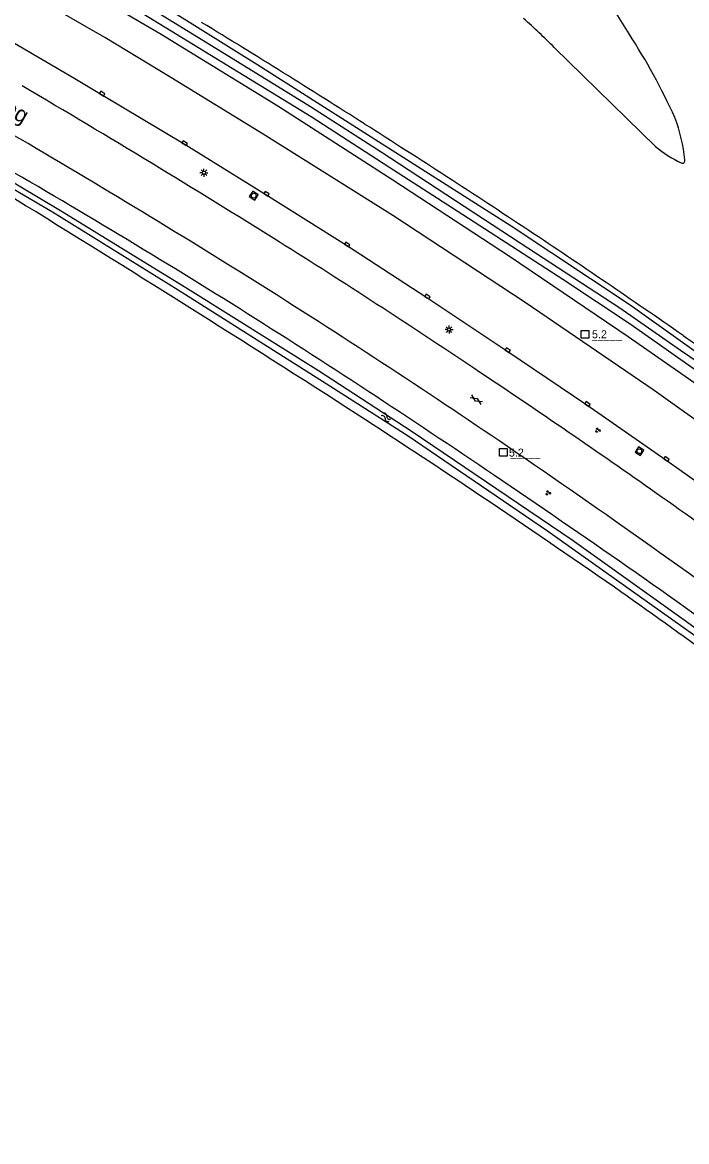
# Model space of a CAD drawing. Extents: x 133000 to 136000, y 400500 to 403500.
# Drawn here: x 134801.3 to 134905.2, y 400816.9 to 400991.7 of the extents above; entities that cross this region are included whole.
import ezdxf

# ---------------------------------------------------------------- set-up
doc = ezdxf.new("R2010")
doc.units = 0
for name, color, linetype in [('gg-afsc-erfafscheiding', 7, 'Continuous'), ('gg-anno-openbare ruimte label', 7, 'Continuous'), ('gg-knt-verharding', 7, 'Continuous'), ('gg-kntw-bovenkant insteek waterloop', 7, 'Continuous'), ('gg-kntw-waterlijn', 7, 'Continuous'), ('gt-anno-nummer hm paal', 7, 'Continuous'), ('gt-symb-gesloten verharding', 7, 'Continuous'), ('gt-symb-groenvak', 7, 'Continuous'), ('gt-symb-hm paal', 7, 'Continuous'), ('gt-symb-kolk', 7, 'Continuous'), ('gt-symb-lichtmast', 7, 'Continuous'), ('gt-symb-rioolschacht', 7, 'Continuous'), ('gt-symb-watersymbool', 7, 'Continuous')]:
    doc.layers.add(name, color=color, linetype=linetype)

# ---------------------------------------------------------------- blocks, each defined once
blk = doc.blocks.new('gt0-RS')
at = {"layer": 'gt-symb-rioolschacht'}
blk.add_lwpolyline([(-0.5, -0.5), (0.5, -0.5), (0.5, 0.5), (-0.5, 0.5)], close=True, dxfattribs=at)
blk.add_circle((0, 0), 0.375, dxfattribs=at)
blk = doc.blocks.new('gt0-KOLK')
at = {"layer": 'gt-symb-kolk'}
blk.add_lwpolyline([(0, 0), (0.38, 0), (0.38, 0.4), (-0.37, 0.4), (-0.37, 0), (0, 0)], dxfattribs=at)
blk = doc.blocks.new('gt0-LMAST')
at = {"layer": 'gt-symb-lichtmast'}
for p, q in [((-0.18, 0.17), (-0.45, 0.44)), ((-0.01, 0.25), (-0.01, 0.62)), ((0.17, 0.17), (0.44, 0.44)), ((-0.26, 0), (-0.63, 0)), ((-0.18, -0.18), (-0.45, -0.45)), ((-0.01, -0.25), (-0.01, -0.63)), ((0.44, -0.45), (0.17, -0.18)), ((0.24, 0), (0.62, 0))]:
    blk.add_line(p, q, dxfattribs=at)
blk.add_circle((-0.01, 0), 0.25, dxfattribs=at)
blk = doc.blocks.new('gt0-WA')
at = {"layer": 'gt-symb-watersymbool'}
for centre, start, end in [((-0.32, 0.02), 28.0725, 151.9275), ((0.43, 0.42), 208.0725, 331.9275), ((-0.32, -0.43), 28.0725, 151.9275), ((0.43, -0.03), 208.0725, 331.9275)]:
    blk.add_arc(centre, 0.425, start, end, dxfattribs=at)
blk = doc.blocks.new('gt0-GESVH1')
at = {"layer": 'gt-symb-gesloten verharding'}
for p, q in [((-0.99, -0.26), (0.01, 0.24)), ((0.01, -0.26), (-0.99, 0.24)), ((0.01, 0.24), (1.01, -0.26)), ((1.01, 0.24), (0.01, -0.26))]:
    blk.add_line(p, q, dxfattribs=at)
blk = doc.blocks.new('gt0-HMpaal')
at = {"layer": 'gt-symb-hm paal'}
blk.add_lwpolyline([(-0.6, 0.6), (0.6, 0.6), (0.6, -0.6), (-0.6, -0.6)], close=True, dxfattribs=at)
blk = doc.blocks.new('gt0-GRVAK')
at = {"layer": 'gt-symb-groenvak'}
for p, q in [((-0.11, 0.19), (-0.23, 0.24)), ((-0.18, 0.15), (0.09, 0.15)), ((-0.09, 0.21), (-0.16, 0.32)), ((-0.05, 0.21), (-0.05, 0.39)), ((0, 0.21), (0.06, 0.32)), ((0.01, 0.19), (0.13, 0.24)), ((0.26, -0.05), (0.2, 0.06)), ((0.3, -0.05), (0.3, 0.13)), ((0.35, -0.05), (0.41, 0.06)), ((-0.25, -0.23), (-0.36, -0.18)), ((-0.32, -0.26), (-0.05, -0.26)), ((-0.23, -0.21), (-0.29, -0.1)), ((-0.18, -0.2), (-0.18, -0.02)), ((-0.14, -0.21), (-0.07, -0.1)), ((-0.12, -0.23), (0, -0.18)), ((0.24, -0.07), (0.12, -0.02)), ((0.17, -0.11), (0.44, -0.11)), ((0.37, -0.07), (0.49, -0.02))]:
    blk.add_line(p, q, dxfattribs=at)

msp = doc.modelspace()

# ---------------------------------------------------------------- linework, layer by layer
at = {"layer": 'gg-afsc-erfafscheiding'}
for centre, radius, start, end in [((133915.2, 399495.67), 1753.25, 57.59278, 58.5737), ((134035.42, 399683.29), 1530.41, 56.48284, 57.62804), ((134114.37, 399807.84), 1382.99, 55.15162, 56.36061), ((133893.12, 399490.22), 1770.06, 54.18342, 55.14896)]:
    msp.add_arc(centre, radius, start, end, dxfattribs=at)
at = {"layer": 'gg-knt-verharding'}
for points in [[(135047.77, 400816.94), (135039.36, 400824.61), (135022.23, 400839.75), (135004.62, 400854.74), (134988.43, 400868.12), (134972.48, 400880.91), (134956.04, 400893.75), (134938.53, 400906.75), (134919.76, 400920.26), (134900.07, 400934.25), (134879.94, 400948), (134859.25, 400961.57), (134838.99, 400974.25), (134824.54, 400983.12), (134814.2, 400989.37), (134794.13, 401000.94), (134771.38, 401013.57), (134759.94, 401019.66)], [(135009.27, 400840.64), (134993.24, 400854.08), (134974.39, 400869.55), (134974.19, 400869.29), (134967.74, 400874.43), (134955.43, 400883.98), (134938.38, 400896.98), (134926.37, 400905.89), (134914.08, 400914.76), (134901.9, 400923.38), (134889.56, 400931.96), (134877.08, 400940.38), (134864.54, 400948.74), (134851.98, 400956.88), (134839.4, 400964.81), (134826.6, 400972.69), (134813.69, 400980.43), (134809.53, 400982.93), (134798.59, 400989.34), (134783.42, 400997.97), (134768.3, 401006.3), (134755.74, 401013.02)]]:
    msp.add_lwpolyline(points, dxfattribs=at)
for centre, radius, start, end in [((133969.14, 399563.62), 1644.31, 57.96001, 59.59591), ((134051.85, 399695.36), 1481.52, 57.96714, 59.79917), ((134177, 399899.65), 1249.19, 56.20005, 57.86522), ((134166.9, 399882.03), 1262.25, 55.75746, 57.90006), ((134153.14, 399857.36), 1297.61, 54.88538, 56.36315), ((133870.54, 399453.84), 1782.99, 53.87087, 55.62745), ((134086.34, 399762.12), 1413.95, 53.45337, 54.89125)]:
    msp.add_arc(centre, radius, start, end, dxfattribs=at)
at = {"layer": 'gg-kntw-bovenkant insteek waterloop'}
msp.add_line((134900.3, 400972.35), (134884.48, 400987.82), dxfattribs=at)
for points in [[(134572.77, 401113.87), (134593.26, 401106.65), (134614.36, 401098.39), (134636.05, 401089.52), (134662.13, 401078.83), (134682.97, 401068.98), (134701.81, 401060.06), (134721.13, 401050.34), (134741.39, 401039.88), (134760.64, 401029.96), (134779.82, 401019.57), (134800.39, 401008.03), (134819.43, 400996.83), (134838.42, 400984.94), (134877.76, 400959.96), (134896.36, 400947.62), (134928.35, 400924.84), (134948.77, 400909.72), (134968.04, 400895.55), (134985.71, 400881.7), (135003.43, 400867.53)], [(134999.15, 400865.39), (134983.55, 400878.24), (134965.57, 400892.51), (134948.44, 400905.63), (134930.21, 400918.86), (134909.59, 400933.18), (134896.02, 400942.64), (134877.47, 400955.17), (134859.24, 400967.08), (134841.26, 400978.65), (134823.05, 400989.84), (134797.2, 401004.96), (134777.3, 401016.05), (134757.03, 401026.72), (134733.14, 401038.94), (134701.13, 401054.6), (134682.13, 401063.5), (134663.52, 401072), (134638.58, 401082.34), (134619.62, 401090.08), (134592.99, 401100.44), (134572.42, 401107.64)]]:
    msp.add_lwpolyline(points, dxfattribs=at)
for centre, radius, start, end in [((134814.33, 400941.24), 95.23, 30.7525, 40.2255), ((134808.94, 400912.57), 106.62, 44.8952, 48.4245), ((134810.17, 400934.3), 102.43, 24.558, 32.9022), ((134879.23, 400967.74), 25.77, 5.5682, 20.749), ((134910.82, 400984.51), 16.07, 229.1389, 246.5177), ((134142.58, 399837.92), 1307.65, 58.01334, 60.0775), ((134904.52, 400970.13), 0.377, 253.4707, 16.8954), ((133284.24, 398494.01), 2898.21, 57.24758, 58.50364), ((134114.25, 399801), 1353.97, 55.80791, 57.824), ((134056.8, 399699.97), 1466.02, 55.1806, 57.14228), ((134061.86, 399713.13), 1456.11, 54.05853, 56.04609), ((134335.56, 400105.77), 973.71, 52.7227, 55.01206)]:
    msp.add_arc(centre, radius, start, end, dxfattribs=at)
at = {"layer": 'gg-kntw-waterlijn'}
for points in [[(134553.93, 401080.85), (134580.74, 401071.1), (134620.81, 401055.21), (134648.59, 401043.73), (134667.94, 401035.01), (134696.91, 401021.89), (134709.26, 401015.83), (134729.42, 401005.45), (134760.81, 400988.75), (134781.03, 400977.76), (134794.05, 400970.2), (134807.28, 400962.36), (134827.55, 400949.89), (134847.62, 400937.36), (134862.09, 400927.93), (134887.28, 400910.92), (134905.15, 400898.15), (134912.66, 400892.68), (134918.69, 400887.99), (134936.81, 400874.32), (134956.11, 400859.39), (134963.66, 400853.39)], [(134963.66, 400853.39), (134962.85, 400852.78), (134943.74, 400867.77), (134929.23, 400878.97), (134908.24, 400894.66), (134883.41, 400912.28), (134861.64, 400927.11), (134848.82, 400935.28), (134825.71, 400949.92), (134806.05, 400962.09), (134796.93, 400967.4), (134781.18, 400976.67), (134767.91, 400983.83), (134746.48, 400995.4), (134729.05, 401004.43), (134702.38, 401018.12), (134677.91, 401029.16), (134657.97, 401038.1), (134644.68, 401043.88), (134627.02, 401051.21), (134592.83, 401065.1), (134551.19, 401080.38)], [(134788.76, 401012.89), (134806.22, 401002.88), (134817.4, 400996.47), (134830.22, 400988.55), (134846.36, 400978.57), (134857.44, 400971.52), (134879.17, 400957.32), (134894.75, 400947.15), (134904.21, 400940.53), (134912.63, 400934.81), (134918.23, 400930.69), (134925.52, 400925.59), (134934.62, 400919.23), (134939.57, 400915.46), (134950.59, 400907.34), (134963.57, 400897.45), (134978.12, 400885.91), (134993.2, 400873.96), (135008.25, 400861.04)], [(134999.53, 400867.09), (134990.79, 400874.23), (134984.06, 400879.73), (134970.7, 400890.51), (134952.89, 400904.22), (134943.87, 400910.95), (134934.96, 400917.45), (134921.02, 400927.24), (134907.08, 400937.04), (134896.34, 400944.58), (134885.84, 400951.58), (134877.84, 400956.75), (134868.59, 400962.71), (134858.63, 400969.14), (134846.46, 400977), (134820.18, 400993.09), (134808.91, 400999.83), (134798.33, 401005.96)]]:
    msp.add_lwpolyline(points, dxfattribs=at)

# ---------------------------------------------------------------- block references
at = {"layer": 'gt-symb-gesloten verharding', "rotation": -33.8330286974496}
msp.add_blockref('gt0-GESVH1', (134872.3, 400932.82), dxfattribs=at)
at = {"layer": 'gt-symb-groenvak'}
for p in [(134891.27, 400928.03), (134883.51, 400918.25)]:
    msp.add_blockref('gt0-GRVAK', p, dxfattribs=at)
at = {"layer": 'gt-symb-hm paal'}
for p in [(134889.3, 400943.01), (134876.53, 400924.58)]:
    msp.add_blockref('gt0-HMpaal', p, dxfattribs=at)
at = {"layer": 'gt-symb-kolk'}
for p, rotation in [((134813.69, 400980.43), -31.38612476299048), ((134826.6, 400972.69), -30.924459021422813), ((134839.4, 400964.81), -31.671318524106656), ((134851.98, 400956.88), -32.211897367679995), ((134864.54, 400948.74), -32.95900987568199), ((134877.08, 400940.38), -33.70595653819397), ((134889.56, 400931.96), -33.99203971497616), ((134901.9, 400923.38), -34.818354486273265)]:
    msp.add_blockref('gt0-KOLK', p, dxfattribs=dict(at, rotation=rotation))
at = {"layer": 'gt-symb-lichtmast'}
for p in [(134829.73, 400968.25), (134868.04, 400943.77)]:
    msp.add_blockref('gt0-LMAST', p, dxfattribs=at)
at = {"layer": 'gt-symb-rioolschacht'}
for p, rotation in [((134837.5, 400964.66), 146.96171538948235), ((134897.79, 400924.76), 148.32868147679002)]:
    msp.add_blockref('gt0-RS', p, dxfattribs=dict(at, rotation=rotation))
at = {"layer": 'gt-symb-watersymbool', "rotation": -33.833028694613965}
msp.add_blockref('gt0-WA', (134858.12, 400930.08), dxfattribs=at)

# ---------------------------------------------------------------- texts
at = {"layer": 'gg-anno-openbare ruimte label'}
msp.add_text('Burgemeester Bechtweg', height=2.5, rotation=330, dxfattribs=at).set_placement((134769.72, 400994.13))
at = {"layer": 'gt-anno-nummer hm paal'}
for p in [(134890.38, 400942.4), (134877.39, 400923.92)]:
    msp.add_text('5.2', height=1.25, dxfattribs=at).set_placement(p)
at = {"layer": 'gt-symb-hm paal'}
for p in [(134890.38, 400942.4), (134877.61, 400923.97)]:
    msp.add_text('_____', height=1.25, dxfattribs=at).set_placement(p)

doc.saveas('drawing.dxf')
